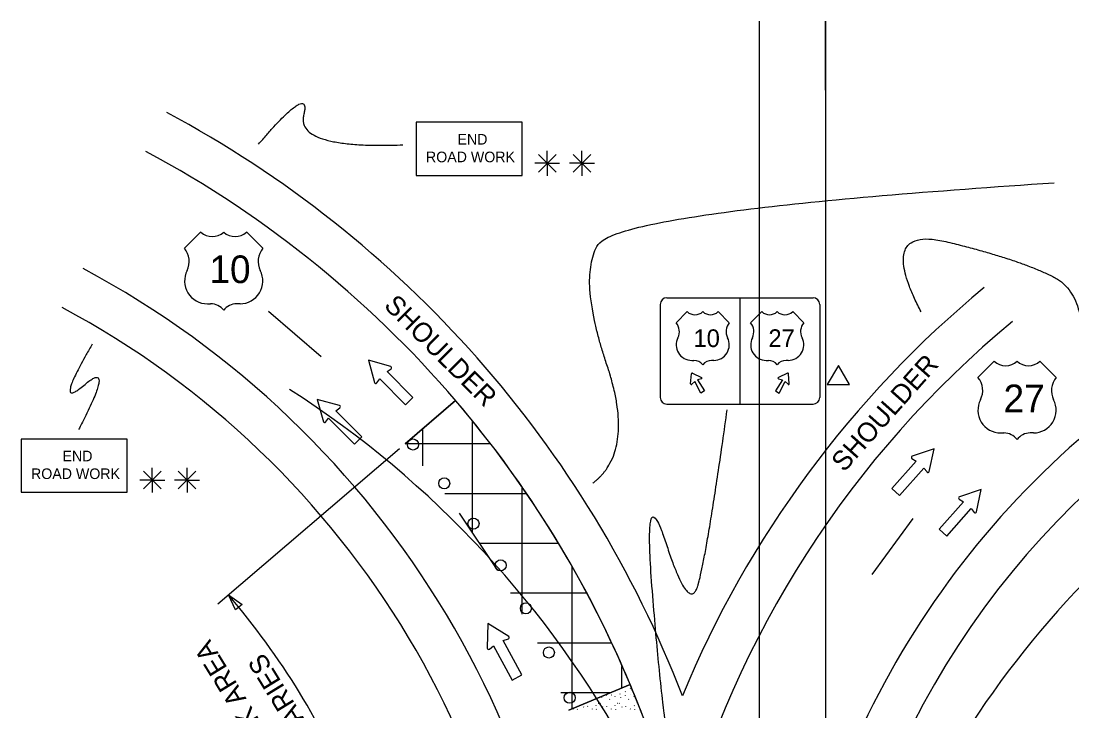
# Model space of a CAD drawing. Extents: x 16476 to 18475, y 6827 to 8243.
# Drawn here: x 16729.3 to 17109, y 7993.9 to 8243.2 of the extents above; entities that cross this region are included whole.
import ezdxf

# ---------------------------------------------------------------- set-up
doc = ezdxf.new("R2010")
doc.units = 0
for name, color, linetype in [('ALI_LEGAL_EX', 7, 'Continuous'), ('MT_SCRATCH_LEVEL_A', 7, 'Continuous'), ('MT_SCRATCH_LEVEL_E', 7, 'Continuous'), ('PAVT_EDGE_EX', 7, 'Continuous'), ('TRAFFIC_SIGNS_PR', 7, 'Continuous'), ('TYPICAL_EX', 7, 'Continuous'), ('TYPICAL_TEXT_DIMEN_PR', 7, 'Continuous')]:
    doc.layers.add(name, color=color, linetype=linetype)

msp = doc.modelspace()

# ---------------------------------------------------------------- linework, layer by layer
at = {"layer": 'ALI_LEGAL_EX'}
for p, q in [((16995.95, 8243.16), (16995.95, 7425.02)), ((17019.95, 8243.16), (17019.95, 7425.02))]:
    msp.add_line(p, q, dxfattribs=at)
for points in [[(17019.95, 8218.16), (17019.95, 8243.16)], [(16837.72, 8121.78), (16818.7, 8138.15)], [(16901.56, 8044.61), (16887.65, 8065.38)], [(17036.81, 8043.22), (17051.56, 8063.4)]]:
    msp.add_lwpolyline(points, dxfattribs=at)
for centre, radius, start, end in [((16629.65, 7803.75), 364, 0, 57.2958), ((17357.65, 7803.75), 340, 129.5666, 180)]:
    msp.add_arc(centre, radius, start, end, dxfattribs=at)
at = {"layer": 'MT_SCRATCH_LEVEL_A'}
for p, q in [((16868.05, 8090.4), (16886.3, 8105.99)), ((16886.3, 8105.99), (16868.05, 8090.4)), ((16874.4, 8082.47), (16874.4, 8095.82)), ((16892.4, 8058.26), (16892.4, 8098.43)), ((16868.16, 8090.49), (16898.69, 8090.49)), ((16910.4, 8028.79), (16910.4, 8074.37)), ((16882.4, 8072.49), (16911.72, 8072.49)), ((16895.05, 8054.49), (16923.26, 8054.49)), ((16928.4, 7994.62), (16928.4, 8046.06)), ((16906.14, 8036.49), (16933.49, 8036.49)), ((16915.86, 8018.49), (16942.53, 8018.49)), ((16946.4, 8002.14), (16946.4, 8009.95)), ((16927.23, 7994.14), (16949.38, 8003.38)), ((16927.23, 7994.14), (16949.38, 8003.38)), ((16949.38, 8003.38), (16927.23, 7994.14)), ((16947.6, 8000.86), (16947.65, 8000.79)), ((16949.39, 8001.93), (16949.44, 8001.85)), ((16924.35, 8000.49), (16942.45, 8000.49)), ((16938.97, 7998.8), (16939.03, 7998.72)), ((16940.75, 7999.47), (16940.81, 7999.58)), ((16941.93, 7997.96), (16941.98, 7998.08)), ((16942.55, 7999.72), (16942.6, 7999.64)), ((16943.83, 7999.14), (16943.84, 7999.02)), ((16945.67, 8000), (16945.72, 8000.11)), ((16945.86, 7998.8), (16945.91, 7998.72)), ((16947.64, 7999.47), (16947.69, 7999.58)), ((16948.82, 7997.96), (16948.87, 7998.08)), ((16949.44, 7999.72), (16949.49, 7999.64)), ((16950.72, 7999.14), (16950.73, 7999.02)), ((16928.73, 7994.64), (16928.78, 7994.56)), ((16930.26, 7994.5), (16930.31, 7994.42)), ((16932.55, 7995.32), (16932.6, 7995.24)), ((16933.99, 7995.47), (16934.05, 7995.59)), ((16935.61, 7994.64), (16935.67, 7994.56)), ((16937.06, 7995.77), (16937.12, 7995.88)), ((16937.14, 7994.5), (16937.19, 7994.42)), ((16937.83, 7996.73), (16937.88, 7996.65)), ((16938.56, 7996.7), (16938.62, 7996.62)), ((16939.43, 7995.32), (16939.49, 7995.24)), ((16940.88, 7995.47), (16940.93, 7995.59)), ((16942.5, 7994.64), (16942.55, 7994.56)), ((16943.95, 7995.77), (16944, 7995.88)), ((16944.03, 7994.5), (16944.08, 7994.42)), ((16944.72, 7996.73), (16944.77, 7996.65)), ((16945.45, 7996.7), (16945.5, 7996.62)), ((16946.32, 7995.32), (16946.37, 7995.24)), ((16947.77, 7995.47), (16947.82, 7995.59)), ((16949.39, 7994.64), (16949.44, 7994.56)), ((16950.84, 7995.77), (16950.89, 7995.88)), ((16950.92, 7994.5), (16950.97, 7994.42)), ((16951.6, 7996.73), (16951.65, 7996.65))]:
    msp.add_line(p, q, dxfattribs=at)
for start, end in [(22.6538, 40.5126), (17.974, 22.6538)]:
    msp.add_arc((16591.32, 7853.94), 388, start, end, dxfattribs=at)
at = {"layer": 'MT_SCRATCH_LEVEL_E'}
for p, q in [((16862.86, 8118.37), (16854.81, 8120.56)), ((16854.81, 8120.56), (16857.02, 8112.53)), ((16861.53, 8116.51), (16863.01, 8117.54)), ((16870.89, 8107.13), (16861.53, 8116.51)), ((16857.84, 8112.39), (16858.88, 8113.87)), ((16858.88, 8113.87), (16868.24, 8104.49)), ((16868.24, 8104.49), (16870.89, 8107.13)), ((16836.31, 8106.4), (16838.51, 8098.37)), ((16844.35, 8104.21), (16836.31, 8106.4)), ((16836.31, 8106.4), (16838.51, 8098.37)), ((16844.35, 8104.21), (16836.31, 8106.4)), ((16843.02, 8102.35), (16844.5, 8103.38)), ((16843.02, 8102.35), (16844.5, 8103.38)), ((16839.34, 8098.23), (16840.37, 8099.71)), ((16839.34, 8098.23), (16840.37, 8099.71)), ((16840.37, 8099.71), (16849.74, 8090.32)), ((16840.37, 8099.71), (16849.74, 8090.32)), ((16852.39, 8092.97), (16843.02, 8102.35)), ((16852.39, 8092.97), (16843.02, 8102.35)), ((16849.74, 8090.32), (16852.39, 8092.97)), ((16849.74, 8090.32), (16852.39, 8092.97)), ((17059.15, 8088.58), (17051.26, 8085.9)), ((17057.44, 8080.41), (17059.15, 8088.58)), ((17051.17, 8085.07), (17052.71, 8084.12)), ((17052.71, 8084.12), (17043.9, 8074.21)), ((17046.7, 8071.73), (17055.51, 8081.64)), ((17055.51, 8081.64), (17056.62, 8080.22)), ((17043.9, 8074.21), (17046.7, 8071.73)), ((17076.23, 8073.92), (17068.35, 8071.24)), ((17074.52, 8065.76), (17076.23, 8073.92)), ((17069.79, 8069.47), (17060.99, 8059.55)), ((17068.25, 8070.41), (17069.79, 8069.47)), ((17063.78, 8057.07), (17072.59, 8066.98)), ((17072.59, 8066.98), (17073.71, 8065.56)), ((17060.99, 8059.55), (17063.78, 8057.07))]:
    msp.add_line(p, q, dxfattribs=at)
for centre, start, end in [((16862.73, 8117.92), 304.9846, 74.7216), ((16857.47, 8112.66), 195.3733, 324.9122), ((16844.22, 8103.76), 304.9845, 74.7214), ((16844.22, 8103.76), 304.9845, 74.7214), ((16838.96, 8098.5), 195.3732, 324.9121), ((16838.96, 8098.5), 195.3732, 324.9121), ((17051.42, 8085.46), 108.8028, 238.3418), ((17056.98, 8080.52), 218.4141, 348.1511), ((17068.5, 8070.8), 108.8028, 238.3418), ((17074.07, 8065.86), 218.4141, 348.1511)]:
    msp.add_arc(centre, 0.463, start, end, dxfattribs=at)
at = {"layer": 'PAVT_EDGE_EX'}
for centre, radius, start, end in [((16591.32, 7853.94), 404, 21.0961, 61.8477), ((16591.32, 7853.94), 388, 17.7215, 61.8477), ((16591.32, 7853.94), 340, 0, 61.8477), ((17319.32, 7853.94), 380, 129.5666, 157.5011), ((16591.32, 7853.94), 324, 0, 61.8477), ((17319.32, 7853.94), 364, 129.5666, 165.0045), ((17319.32, 7853.94), 316, 129.5666, 180), ((17319.32, 7853.94), 300, 129.5666, 180)]:
    msp.add_arc(centre, radius, start, end, dxfattribs=at)
at = {"layer": 'TRAFFIC_SIGNS_PR'}
for p, q in [((16962.64, 8143.15), (17015.45, 8143.15)), ((16989.04, 8143.15), (16989.04, 8104.74)), ((16960.24, 8140.75), (16960.24, 8107.14)), ((17017.85, 8140.75), (17017.85, 8107.14)), ((16971.22, 8112.09), (16971.5, 8115.72)), ((16971.88, 8115.93), (16975.15, 8114.36)), ((17006.21, 8115.93), (17002.93, 8114.36)), ((17006.87, 8112.09), (17006.58, 8115.72)), ((16962.64, 8104.74), (17015.45, 8104.74))]:
    msp.add_line(p, q, dxfattribs=at)
for points in [[(16871.99, 8187.38), (16910.39, 8187.38), (16910.39, 8206.58), (16871.99, 8206.58)], [(16729.28, 8072.93), (16767.68, 8072.93), (16767.68, 8092.13), (16729.28, 8092.13)]]:
    msp.add_lwpolyline(points, close=True, dxfattribs=at)
for points in [[(16975.11, 8113.88), (16973.7, 8113.49), (16976.22, 8109.51), (16974.89, 8108.74), (16972.7, 8112.91), (16971.66, 8111.89)], [(17002.97, 8113.88), (17004.38, 8113.49), (17001.87, 8109.51), (17003.19, 8108.74), (17005.39, 8112.91), (17006.42, 8111.89)]]:
    msp.add_lwpolyline(points, dxfattribs=at)
for centre in [(16870.91, 8090.14), (16882.18, 8076.11), (16892.75, 8061.55), (16902.59, 8046.48), (16911.69, 8030.92), (16920, 8014.98), (16927.51, 7998.63)]:
    msp.add_circle(centre, 2, dxfattribs=at)
for centre, radius, start, end in [((16962.64, 8140.75), 2.4, 90, 180), ((16962.64, 8140.75), 2.4, 90, 180), ((17015.45, 8140.75), 2.4, 0, 90), ((16971.76, 8115.7), 0.26, 64.4823, 175.5177), ((17006.32, 8115.7), 0.26, 4.4823, 115.5177), ((16971.48, 8112.07), 0.26, 175.5177, 314.0115), ((16975.04, 8114.13), 0.26, 285.9885, 64.4823), ((17003.04, 8114.13), 0.26, 115.5177, 254.0115), ((17006.61, 8112.07), 0.26, 225.9885, 4.4823), ((16962.64, 8107.14), 2.4, 180, 270), ((17015.45, 8107.14), 2.4, 270, 0)]:
    msp.add_arc(centre, radius, start, end, dxfattribs=at)
at = {"layer": 'TYPICAL_EX'}
for p, q in [((16788.35, 8161.03), (16794.24, 8166.93)), ((16816.65, 8161.03), (16810.75, 8166.93)), ((16796.6, 8140.97), (16797.77, 8140.97)), ((16808.4, 8140.97), (16807.22, 8140.97)), ((16965.99, 8134.15), (16969.99, 8138.15)), ((16985.19, 8134.15), (16981.19, 8138.15)), ((16992.89, 8134.15), (16996.89, 8138.15)), ((17012.1, 8134.15), (17008.09, 8138.15)), ((16971.59, 8120.53), (16972.39, 8120.53)), ((16979.6, 8120.53), (16978.8, 8120.53)), ((16998.49, 8120.53), (16999.29, 8120.53)), ((17006.5, 8120.53), (17005.7, 8120.53)), ((17075.01, 8114.36), (17080.91, 8120.26)), ((17103.31, 8114.36), (17097.42, 8120.26)), ((17083.26, 8094.31), (17084.44, 8094.31)), ((17095.07, 8094.31), (17093.89, 8094.31))]:
    msp.add_line(p, q, dxfattribs=at)
for centre, radius, start, end in [((16798.37, 8171.22), 5.96, 226.1404, 313.8596), ((16806.63, 8171.22), 5.96, 226.1404, 313.8596), ((16782.76, 8156.31), 7.31, 333.0977, 40.1936), ((16822.24, 8156.31), 7.31, 139.8064, 206.9023), ((16796.61, 8149.22), 8.24, 152.6698, 269.9013), ((16808.39, 8149.22), 8.24, 270.0987, 27.3302), ((16797.79, 8135.07), 5.91, 37.1038, 90.1385), ((16807.21, 8135.07), 5.91, 89.8615, 142.8962), ((16972.79, 8141.06), 4.04, 226.1404, 313.8596), ((16978.39, 8141.06), 4.04, 226.1404, 313.8596), ((16999.69, 8141.06), 4.04, 226.1404, 313.8596), ((17005.29, 8141.06), 4.04, 226.1404, 313.8596), ((16962.2, 8130.94), 4.96, 333.0977, 40.1936), ((16988.98, 8130.94), 4.96, 139.8064, 206.9023), ((16989.1, 8130.94), 4.96, 333.0977, 40.1936), ((17015.89, 8130.94), 4.96, 139.8064, 206.9023), ((16971.6, 8126.13), 5.59, 152.6698, 269.9013), ((16979.59, 8126.13), 5.59, 270.0987, 27.3302), ((16998.5, 8126.13), 5.59, 152.6698, 269.9013), ((17006.49, 8126.13), 5.59, 270.0987, 27.3302), ((16972.4, 8116.53), 4.01, 37.1038, 90.1385), ((16978.79, 8116.53), 4.01, 89.8615, 142.8962), ((16999.3, 8116.53), 4.01, 37.1038, 90.1385), ((17005.69, 8116.53), 4.01, 89.8615, 142.8962), ((17085.04, 8124.55), 5.96, 226.1404, 313.8596), ((17093.29, 8124.55), 5.96, 226.1404, 313.8596), ((17069.43, 8109.64), 7.31, 333.0977, 40.1936), ((17108.9, 8109.64), 7.31, 139.8064, 206.9023), ((17083.27, 8102.55), 8.24, 152.6698, 269.9013), ((17095.05, 8102.55), 8.24, 270.0987, 27.3302), ((17084.45, 8088.4), 5.91, 37.1038, 90.1385), ((17093.87, 8088.4), 5.91, 89.8615, 142.8962)]:
    msp.add_arc(centre, radius, start, end, dxfattribs=at)
at = {"layer": 'TYPICAL_TEXT_DIMEN_PR'}
for p, q in [((16916.22, 8194.94), (16922.6, 8188.57)), ((16922.6, 8194.94), (16916.22, 8188.57)), ((16919.41, 8191.76), (16919.41, 8196.21)), ((16928.78, 8194.94), (16935.15, 8188.57)), ((16935.15, 8194.94), (16928.78, 8188.57)), ((16931.96, 8191.76), (16931.96, 8196.21)), ((16919.41, 8191.76), (16914.88, 8191.76)), ((16919.41, 8191.76), (16922.6, 8191.76)), ((16919.41, 8191.76), (16923.89, 8191.76)), ((16919.41, 8191.76), (16919.41, 8187.26)), ((16931.96, 8191.76), (16927.43, 8191.76)), ((16931.96, 8191.76), (16935.15, 8191.76)), ((16931.96, 8191.76), (16936.44, 8191.76)), ((16931.96, 8191.76), (16931.96, 8187.26)), ((16800.39, 8032.58), (16866.03, 8088.67)), ((16776.7, 8077.3), (16776.7, 8081.76)), ((16789.25, 8077.3), (16789.25, 8081.76)), ((16776.7, 8077.3), (16772.17, 8077.3)), ((16773.51, 8080.49), (16779.89, 8074.11)), ((16779.89, 8080.49), (16773.51, 8074.11)), ((16776.7, 8077.3), (16779.89, 8077.3)), ((16776.7, 8077.3), (16781.18, 8077.3)), ((16776.7, 8077.3), (16776.7, 8072.8)), ((16789.25, 8077.3), (16784.72, 8077.3)), ((16786.07, 8080.49), (16792.44, 8074.11)), ((16792.44, 8080.49), (16786.07, 8074.11)), ((16789.25, 8077.3), (16792.44, 8077.3)), ((16789.25, 8077.3), (16793.73, 8077.3)), ((16789.25, 8077.3), (16789.25, 8072.8)), ((16806.8, 8030.35), (16804.19, 8035.83)), ((16804.19, 8035.83), (16809.19, 8032.39)), ((16808, 8031.37), (16806.8, 8030.35)), ((16809.19, 8032.39), (16808, 8031.37)), ((16897.9, 8025.49), (16897.73, 8016.62)), ((16905.47, 8020.81), (16897.9, 8025.49)), ((16903.54, 8019.32), (16905.37, 8019.93)), ((16898.53, 8016.22), (16900.03, 8017.42)), ((16900.03, 8017.42), (16906.77, 8004.98)), ((16910.28, 8006.88), (16903.54, 8019.32)), ((16906.77, 8004.98), (16910.28, 8006.88))]:
    msp.add_line(p, q, dxfattribs=at)
msp.add_lwpolyline([(17024.6, 8118.74), (17020.58, 8111.78), (17028.62, 8111.78)], close=True, dxfattribs=at)
for centre, radius, start, end in [((16591.32, 7853.94), 280, 22.6539, 40.5126), ((16905.2, 8020.39), 0.494, 288.4717, 58.2087), ((16898.22, 8016.61), 0.494, 178.8604, 308.3994)]:
    msp.add_arc(centre, radius, start, end, dxfattribs=at)
for points in [[(16815.12, 8198.66), (16834.33, 8221.27), (16828.48, 8196.99), (16867.18, 8198.39)], [(16935.84, 8076.15), (16951.41, 8087.85), (16930.65, 8149.63), (16944.27, 8174.35), (17102.55, 8184.75)], [(17054.48, 8138.06), (17038.1, 8169.55), (17089.3, 8157.23), (17115.24, 8144.22), (17109.45, 8091.8), (17158.26, 8096.33)], [(16755, 8126.36), (16740.54, 8101.74), (16763.75, 8121.58), (16750.1, 8095.57)], [(16963.86, 7977.55), (16960.43, 7998.19), (16954.09, 8079.69), (16970.72, 8028.62), (16977.06, 8050.05), (16984.44, 8102.7)]]:
    msp.add_open_spline(points, degree=2, dxfattribs=at)

# ---------------------------------------------------------------- texts
at = {"layer": 'TRAFFIC_SIGNS_PR'}
for s, height, p in [('END', 3.831, (16886.99, 8198.51)), ('ROAD WORK', 3.831, (16875.59, 8192.13)), ('10', 6.401, (16972.25, 8125.35)), ('27', 6.401, (16999.32, 8125.35)), ('END', 3.831, (16744.28, 8084.06)), ('ROAD WORK', 3.831, (16732.89, 8077.67))]:
    msp.add_text(s, height=height, dxfattribs=at).set_placement(p)
at = {"layer": 'TYPICAL_EX'}
for s, p in [('10', (16797.34, 8148.46)), ('27', (17084.27, 8101.79))]:
    msp.add_text(s, height=10, dxfattribs=at).set_placement(p)
at = {"layer": 'TYPICAL_TEXT_DIMEN_PR'}
for s, rotation, p in [('SHOULDER', 315.1182, (16860.07, 8139.97)), ('SHOULDER', 48.378, (17026.67, 8079.89)), ('WORK AREA', 121.5829, (16827.45, 7971.27)), ('VARIES', 121.5829, (16834.85, 7985.96))]:
    msp.add_text(s, height=7, rotation=rotation, dxfattribs=at).set_placement(p)

doc.saveas('drawing.dxf')
